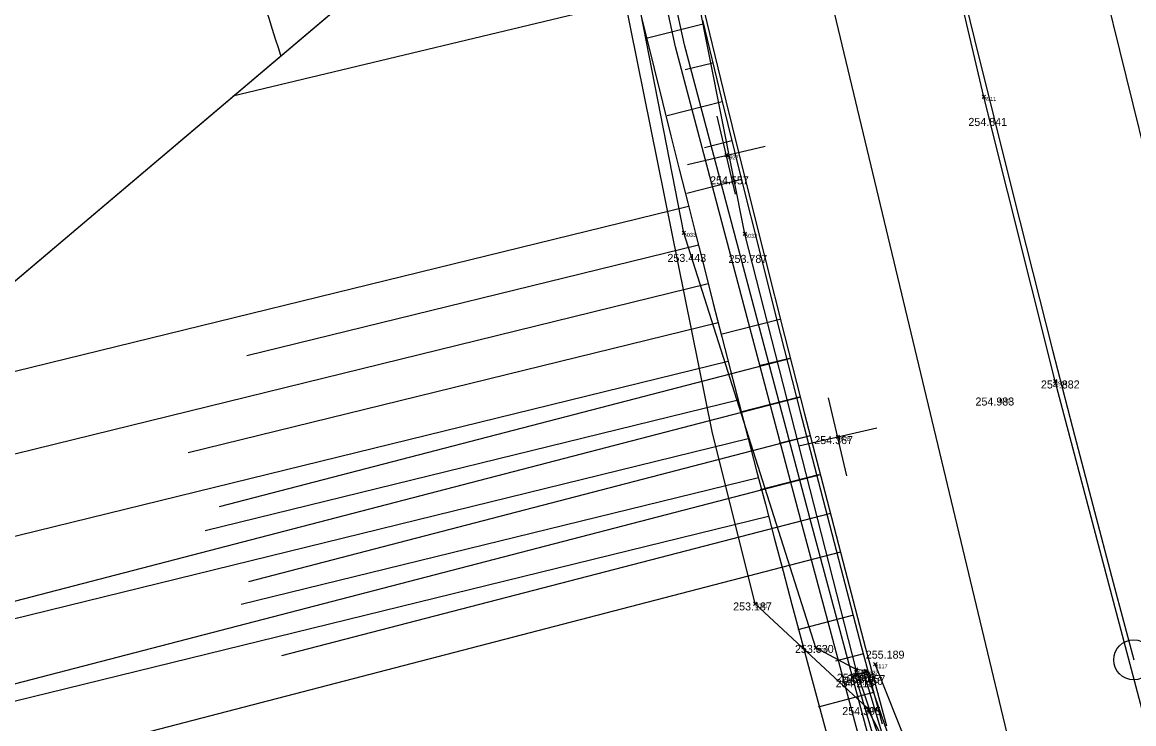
# Model space of a CAD drawing. Extents: x -809973 to -809318, y -1011363 to -1010505.
# Drawn here: x -809855.63 to -809841.74, y -1010978.91 to -1010970.15 of the extents above; entities that cross this region are included whole.
import ezdxf

# ---------------------------------------------------------------- set-up
doc = ezdxf.new("R2010")
doc.units = 0
for name, color, linetype in [('18b - zaměření - čísla bodů', 7, 'Continuous'), ('18c - zaměření - výšky', 7, 'Continuous'), ('21 - sítě', 7, 'Continuous'), ('21a - sítě - DKK - ČD Telematika a.s.', 7, 'Continuous'), ('21b - sítě - SŽDC - SSZT', 7, 'Continuous'), ('Návrh', 7, 'Continuous'), ('SO04 - Železniční spodek', 7, 'Continuous'), ('SO05 - Úprava kabelů', 7, 'Continuous'), ('SO_01', 7, 'Continuous'), ('stav_stav', 7, 'Continuous')]:
    doc.layers.add(name, color=color, linetype=linetype)

# ---------------------------------------------------------------- blocks, each defined once
blk = doc.blocks.new('POINT_DISPLAY')
for p, q in [((-0.021, -0.021), (0.021, 0.021)), ((-0.021, 0.021), (0.021, -0.021))]:
    blk.add_line(p, q)

msp = doc.modelspace()

# ---------------------------------------------------------------- linework, layer by layer
at = {"layer": '21 - sítě'}
for points in [[(-809846.471, -1010977.412), (-809846.471, -1010977.412), (-809847.01, -1010975.259), (-809855.507, -1010933.199), (-809859.779, -1010907.44), (-809863.733, -1010881.556)], [(-809832.875, -1011017.263), (-809833.494, -1011015.746), (-809838.391, -1011005.426), (-809840.703, -1011001.729), (-809840.806, -1011000.123), (-809839.446, -1010997.434), (-809844.081, -1010980.644), (-809845.074, -1010978.711), (-809846.471, -1010977.412)]]:
    msp.add_lwpolyline(points, dxfattribs=at)
at = {"layer": '21a - sítě - DKK - ČD Telematika a.s.'}
for points in [[(-809846.471, -1010977.412), (-809846.471, -1010977.412), (-809847.01, -1010975.259), (-809855.507, -1010933.199), (-809859.779, -1010907.44), (-809863.733, -1010881.556)], [(-809840.802, -1011000.183), (-809839.446, -1010997.434), (-809844.081, -1010980.644), (-809845.074, -1010978.711), (-809846.471, -1010977.412)]]:
    msp.add_lwpolyline(points, dxfattribs=at)
at = {"layer": '21b - sítě - SŽDC - SSZT'}
for points in [[(-809846.471, -1010977.412), (-809846.471, -1010977.412), (-809847.01, -1010975.259), (-809855.507, -1010933.199), (-809859.779, -1010907.44), (-809863.733, -1010881.556)], [(-809840.802, -1011000.183), (-809839.446, -1010997.434), (-809844.081, -1010980.644), (-809845.074, -1010978.711), (-809846.471, -1010977.412)]]:
    msp.add_lwpolyline(points, dxfattribs=at)
at = {"layer": 'Návrh'}
msp.add_lwpolyline([(-809843.968, -1010969.393), (-809843.73, -1010970.365), (-809843.49, -1010971.335), (-809843.247, -1010972.306), (-809843.002, -1010973.275), (-809842.755, -1010974.244), (-809842.505, -1010975.212), (-809842.252, -1010976.18), (-809841.997, -1010977.147), (-809841.74, -1010978.113)], dxfattribs=at)
msp.add_circle((-809841.74, -1010978.113), 0.25, dxfattribs=at)
at = {"layer": 'SO04 - Železniční spodek'}
for points in [[(-809860.526, -1010977.437), (-809847.931, -1010966.781)], [(-809847.131, -1010970.124), (-809846.892, -1010971.103), (-809846.65, -1010972.082), (-809846.405, -1010973.059), (-809846.158, -1010974.037), (-809845.909, -1010975.014), (-809845.657, -1010975.99), (-809845.402, -1010976.966), (-809845.145, -1010977.941), (-809844.886, -1010978.911)], [(-809847.817, -1010970.343), (-809847.121, -1010970.167)], [(-809847.348, -1010970.74), (-809847.002, -1010970.653)], [(-809847.573, -1010971.313), (-809846.883, -1010971.139)], [(-809847.106, -1010971.711), (-809846.763, -1010971.624)], [(-809847.328, -1010972.282), (-809846.643, -1010972.109)], [(-809857.612, -1010974.971), (-809847.305, -1010972.444)], [(-809852.825, -1010974.312), (-809847.182, -1010972.929)], [(-809859.326, -1010976.421), (-809847.058, -1010973.413)], [(-809846.901, -1010974.044), (-809846.162, -1010973.858)], [(-809853.558, -1010975.522), (-809846.934, -1010973.897)], [(-809860.332, -1010977.698), (-809846.809, -1010974.382)], [(-809846.42, -1010974.438), (-809846.043, -1010974.343)], [(-809846.656, -1010975.014), (-809845.924, -1010974.829)], [(-809853.346, -1010976.499), (-809846.684, -1010974.866)], [(-809859.683, -1010978.568), (-809846.558, -1010975.35)], [(-809846.172, -1010975.407), (-809845.803, -1010975.314)], [(-809852.895, -1010977.418), (-809846.432, -1010975.834)], [(-809846.411, -1010975.983), (-809845.682, -1010975.799)], [(-809859.034, -1010979.439), (-809846.305, -1010976.317)], [(-809845.934, -1010977.732), (-809845.238, -1010977.55)], [(-809845.465, -1010978.126), (-809845.114, -1010978.034)], [(-809845.68, -1010978.699), (-809844.989, -1010978.518)]]:
    msp.add_lwpolyline(points, dxfattribs=at)
msp.add_arc((-809453.305, -1010872.818), 406.4, 193.63597, 201.43276, dxfattribs=at)
msp.add_open_spline([(-809852.4, -1010970.562), (-809852.996, -1010968.741), (-809860.472, -1010944.293), (-809865.615, -1010919.474), (-809868.842, -1010894.597), (-809852.698, -1010969.652), (-809867.402, -1010907.056)], degree=3, dxfattribs=at)
at = {"layer": 'SO05 - Úprava kabelů'}
for points in [[(-809832.452, -1011018.3), (-809834.599, -1011012.541), (-809836.558, -1011007.657), (-809839.63, -1011000.177), (-809840.754, -1010995.474), (-809845.885, -1010976.431), (-809847.466, -1010970.457), (-809849.998, -1010958.97), (-809853.746, -1010939.574), (-809862.448, -1010886.367), (-809861.681, -1010881.903), (-809870.184, -1010824.906)], [(-809832.343, -1011018.259), (-809834.49, -1011012.499), (-809836.45, -1011007.613), (-809839.519, -1011000.141), (-809840.641, -1010995.445), (-809845.773, -1010976.401), (-809847.353, -1010970.429), (-809849.884, -1010958.947), (-809853.631, -1010939.554), (-809862.33, -1010886.367), (-809861.563, -1010881.905), (-809870.069, -1010824.889)]]:
    msp.add_lwpolyline(points, dxfattribs=at)
at = {"layer": 'SO_01'}
for p, q in [((-809847.191, -1010969.68), (-809853.001, -1010971.071)), ((-809846.031, -1010974.347), (-809853.172, -1010976.201)), ((-809845.907, -1010974.832), (-809860.032, -1010978.499)), ((-809845.783, -1010975.316), (-809852.803, -1010977.138)), ((-809845.658, -1010975.8), (-809859.503, -1010979.394)), ((-809845.532, -1010976.284), (-809852.392, -1010978.065)), ((-809845.406, -1010976.768), (-809858.889, -1010980.268))]:
    msp.add_line(p, q, dxfattribs=at)
for points in [[(-809860.526, -1010977.437), (-809847.89, -1010966.747)], [(-809847.89, -1010966.747), (-809847.781, -1010967.211), (-809847.549, -1010968.191), (-809847.314, -1010969.171), (-809847.077, -1010970.15), (-809846.837, -1010971.129), (-809846.595, -1010972.108), (-809846.351, -1010973.086), (-809846.104, -1010974.063), (-809845.854, -1010975.04), (-809845.602, -1010976.016), (-809845.348, -1010976.992), (-809845.091, -1010977.967), (-809844.832, -1010978.937)]]:
    msp.add_lwpolyline(points, dxfattribs=at)
at = {"layer": 'stav_stav'}
for p, q in [((-809847.365, -1010972.779), (-809851.193, -1010953.154)), ((-809846.601, -1010972.791), (-809850.517, -1010953.058)), ((-809840.375, -1010976.742), (-809844.107, -1010961.611)), ((-809843.612, -1010971.08), (-809845.723, -1010962.088)), ((-809843.041, -1010980.213), (-809846.285, -1010966.658)), ((-809842.723, -1010974.633), (-809843.612, -1010971.08)), ((-809846.718, -1010972.297), (-809846.946, -1010971.323)), ((-809847.319, -1010971.924), (-809846.345, -1010971.696)), ((-809845.714, -1010977.964), (-809847.365, -1010972.779)), ((-809845.209, -1010978.233), (-809846.601, -1010972.791)), ((-809841.189, -1010980.417), (-809842.723, -1010974.633)), ((-809845.326, -1010975.814), (-809845.554, -1010974.84)), ((-809845.927, -1010975.441), (-809844.953, -1010975.213)), ((-809845.074, -1010978.711), (-809846.471, -1010977.412)), ((-809845.209, -1010978.233), (-809845.714, -1010977.964)), ((-809843.802, -1010981.111), (-809844.97, -1010978.168)), ((-809845.223, -1010978.301), (-809845.209, -1010978.233)), ((-809845.115, -1010978.271), (-809845.223, -1010978.301)), ((-809844.371, -1010981.14), (-809845.223, -1010978.301)), ((-809845.085, -1010978.25), (-809845.209, -1010978.233)), ((-809844.216, -1010981.17), (-809845.209, -1010978.233)), ((-809845.085, -1010978.25), (-809845.209, -1010978.233)), ((-809844.216, -1010981.17), (-809845.209, -1010978.233)), ((-809845.115, -1010978.271), (-809845.085, -1010978.25)), ((-809845.115, -1010978.271), (-809845.085, -1010978.25)), ((-809844.412, -1010980.573), (-809845.115, -1010978.271)), ((-809844.412, -1010980.573), (-809845.115, -1010978.271)), ((-809844.092, -1010981.109), (-809845.085, -1010978.25)), ((-809844.081, -1010980.644), (-809845.074, -1010978.711))]:
    msp.add_line(p, q, dxfattribs=at)

# ---------------------------------------------------------------- block references
at = {"layer": '18b - zaměření - čísla bodů'}
for p in [(-809843.612, -1010971.08), (-809846.832, -1010971.81), (-809847.365, -1010972.779), (-809846.601, -1010972.791), (-809842.723, -1010974.633), (-809845.44, -1010975.327), (-809846.471, -1010977.412), (-809845.714, -1010977.964), (-809844.97, -1010978.168), (-809845.223, -1010978.301), (-809845.209, -1010978.233), (-809845.115, -1010978.271), (-809845.085, -1010978.25), (-809845.074, -1010978.711)]:
    msp.add_blockref('POINT_DISPLAY', p, dxfattribs=at)

# ---------------------------------------------------------------- texts
for s, p in [('4911', (-809843.612, -1010971.13)), ('4927', (-809846.832, -1010971.86)), ('5033', (-809847.365, -1010972.829)), ('5032', (-809846.601, -1010972.841)), ('4908', (-809842.723, -1010974.683)), ('4910', (-809843.434, -1010974.901)), ('4928', (-809845.44, -1010975.377)), ('5031', (-809846.471, -1010977.462)), ('5030', (-809845.714, -1010978.014)), ('5117', (-809844.97, -1010978.218)), ('5025', (-809845.223, -1010978.351)), ('5028', (-809845.209, -1010978.283)), ('5026', (-809845.115, -1010978.321)), ('5027', (-809845.085, -1010978.3)), ('5029', (-809845.074, -1010978.761))]:
    msp.add_text(s, height=0.05, dxfattribs=at).set_placement(p)
at = {"layer": '18c - zaměření - výšky'}
for s, p in [('254.841', (-809843.807, -1010971.443)), ('254.557', (-809847.035, -1010972.173)), ('253.443', (-809847.568, -1010973.142)), ('253.787', (-809846.804, -1010973.154)), ('254.882', (-809842.9, -1010974.723)), ('254.983', (-809843.718, -1010974.936)), ('254.367', (-809845.733, -1010975.418)), ('253.187', (-809846.747, -1010977.496)), ('253.630', (-809845.974, -1010978.027)), ('255.189', (-809845.089, -1010978.098)), ('253.865', (-809845.452, -1010978.387)), ('254.256', (-809845.358, -1010978.425)), ('253.957', (-809845.328, -1010978.404)), ('254.215', (-809845.466, -1010978.455)), ('254.395', (-809845.383, -1010978.803))]:
    msp.add_text(s, height=0.1, dxfattribs=at).set_placement(p)

doc.saveas('drawing.dxf')
